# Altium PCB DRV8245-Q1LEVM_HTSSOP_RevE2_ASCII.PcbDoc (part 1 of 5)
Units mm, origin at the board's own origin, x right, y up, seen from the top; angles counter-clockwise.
Board outline 81.9 x 103.6 mm, 4 copper layers (Top Layer, Signal Layer 1, Signal Layer 2, Bottom Layer), stack 1.554 mm thick; 187 components, 116 nets, 590 pads, 1182 vias.
Unrouted connection lines stored in the file: 116.
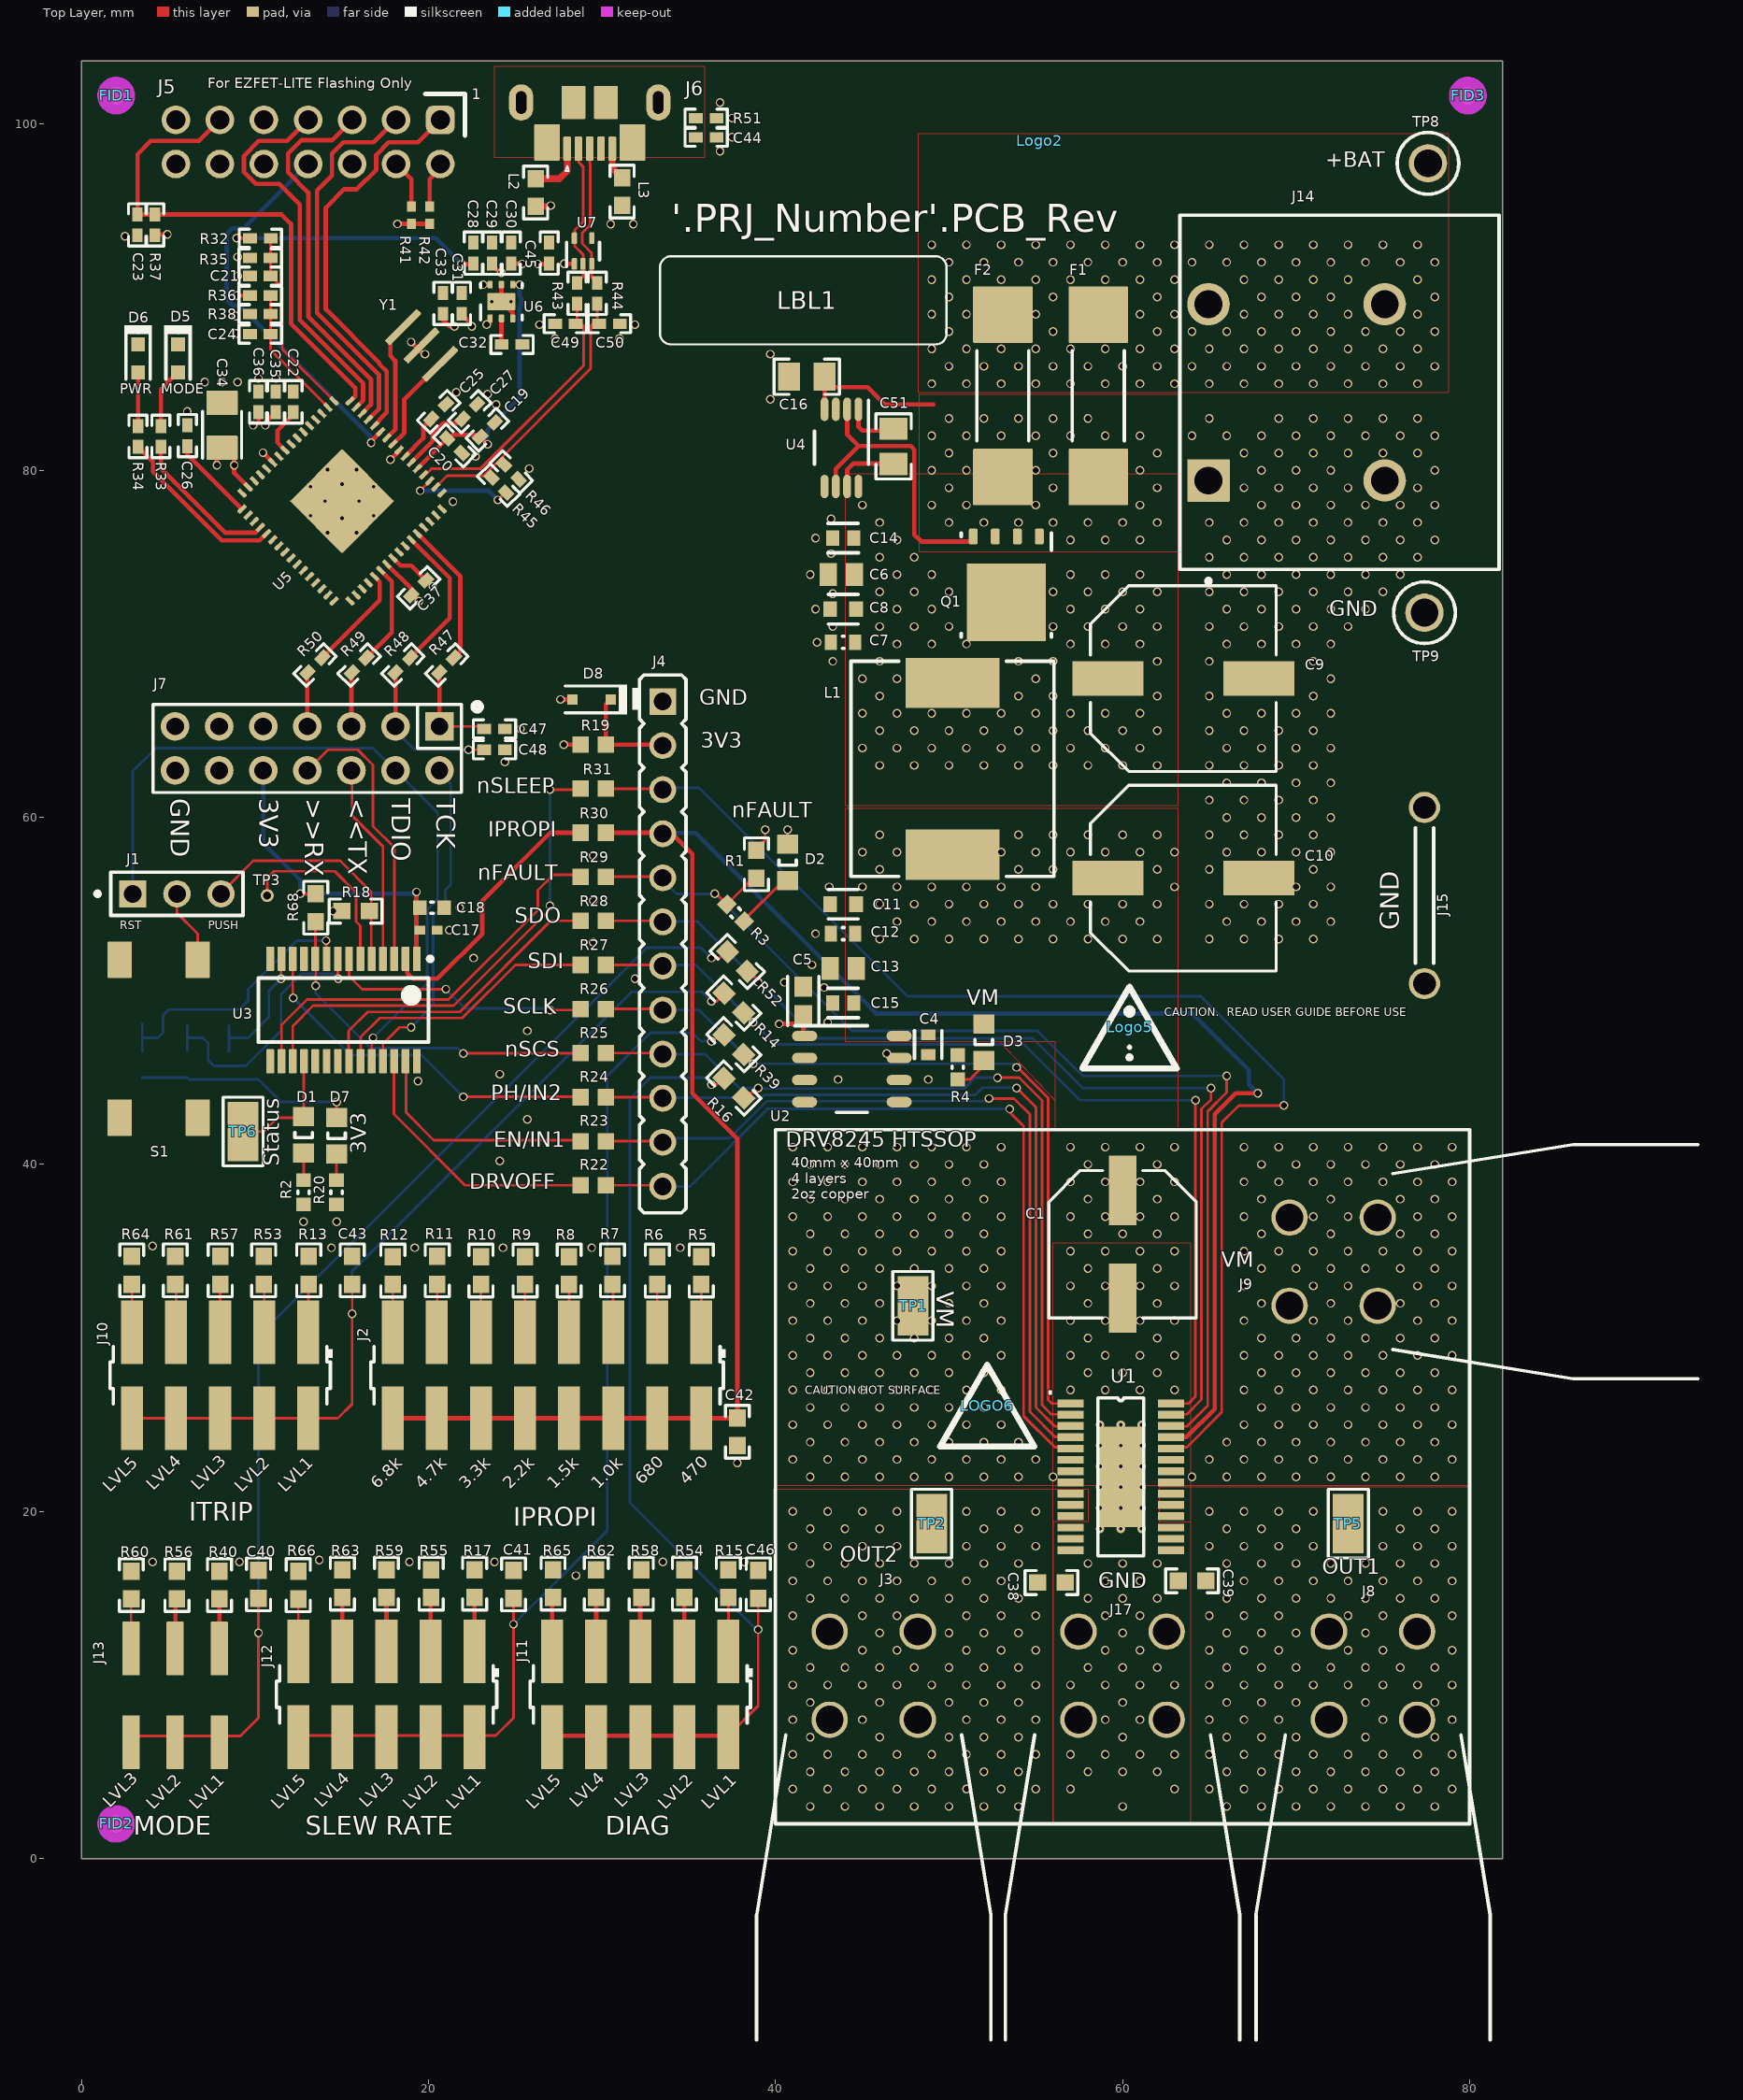
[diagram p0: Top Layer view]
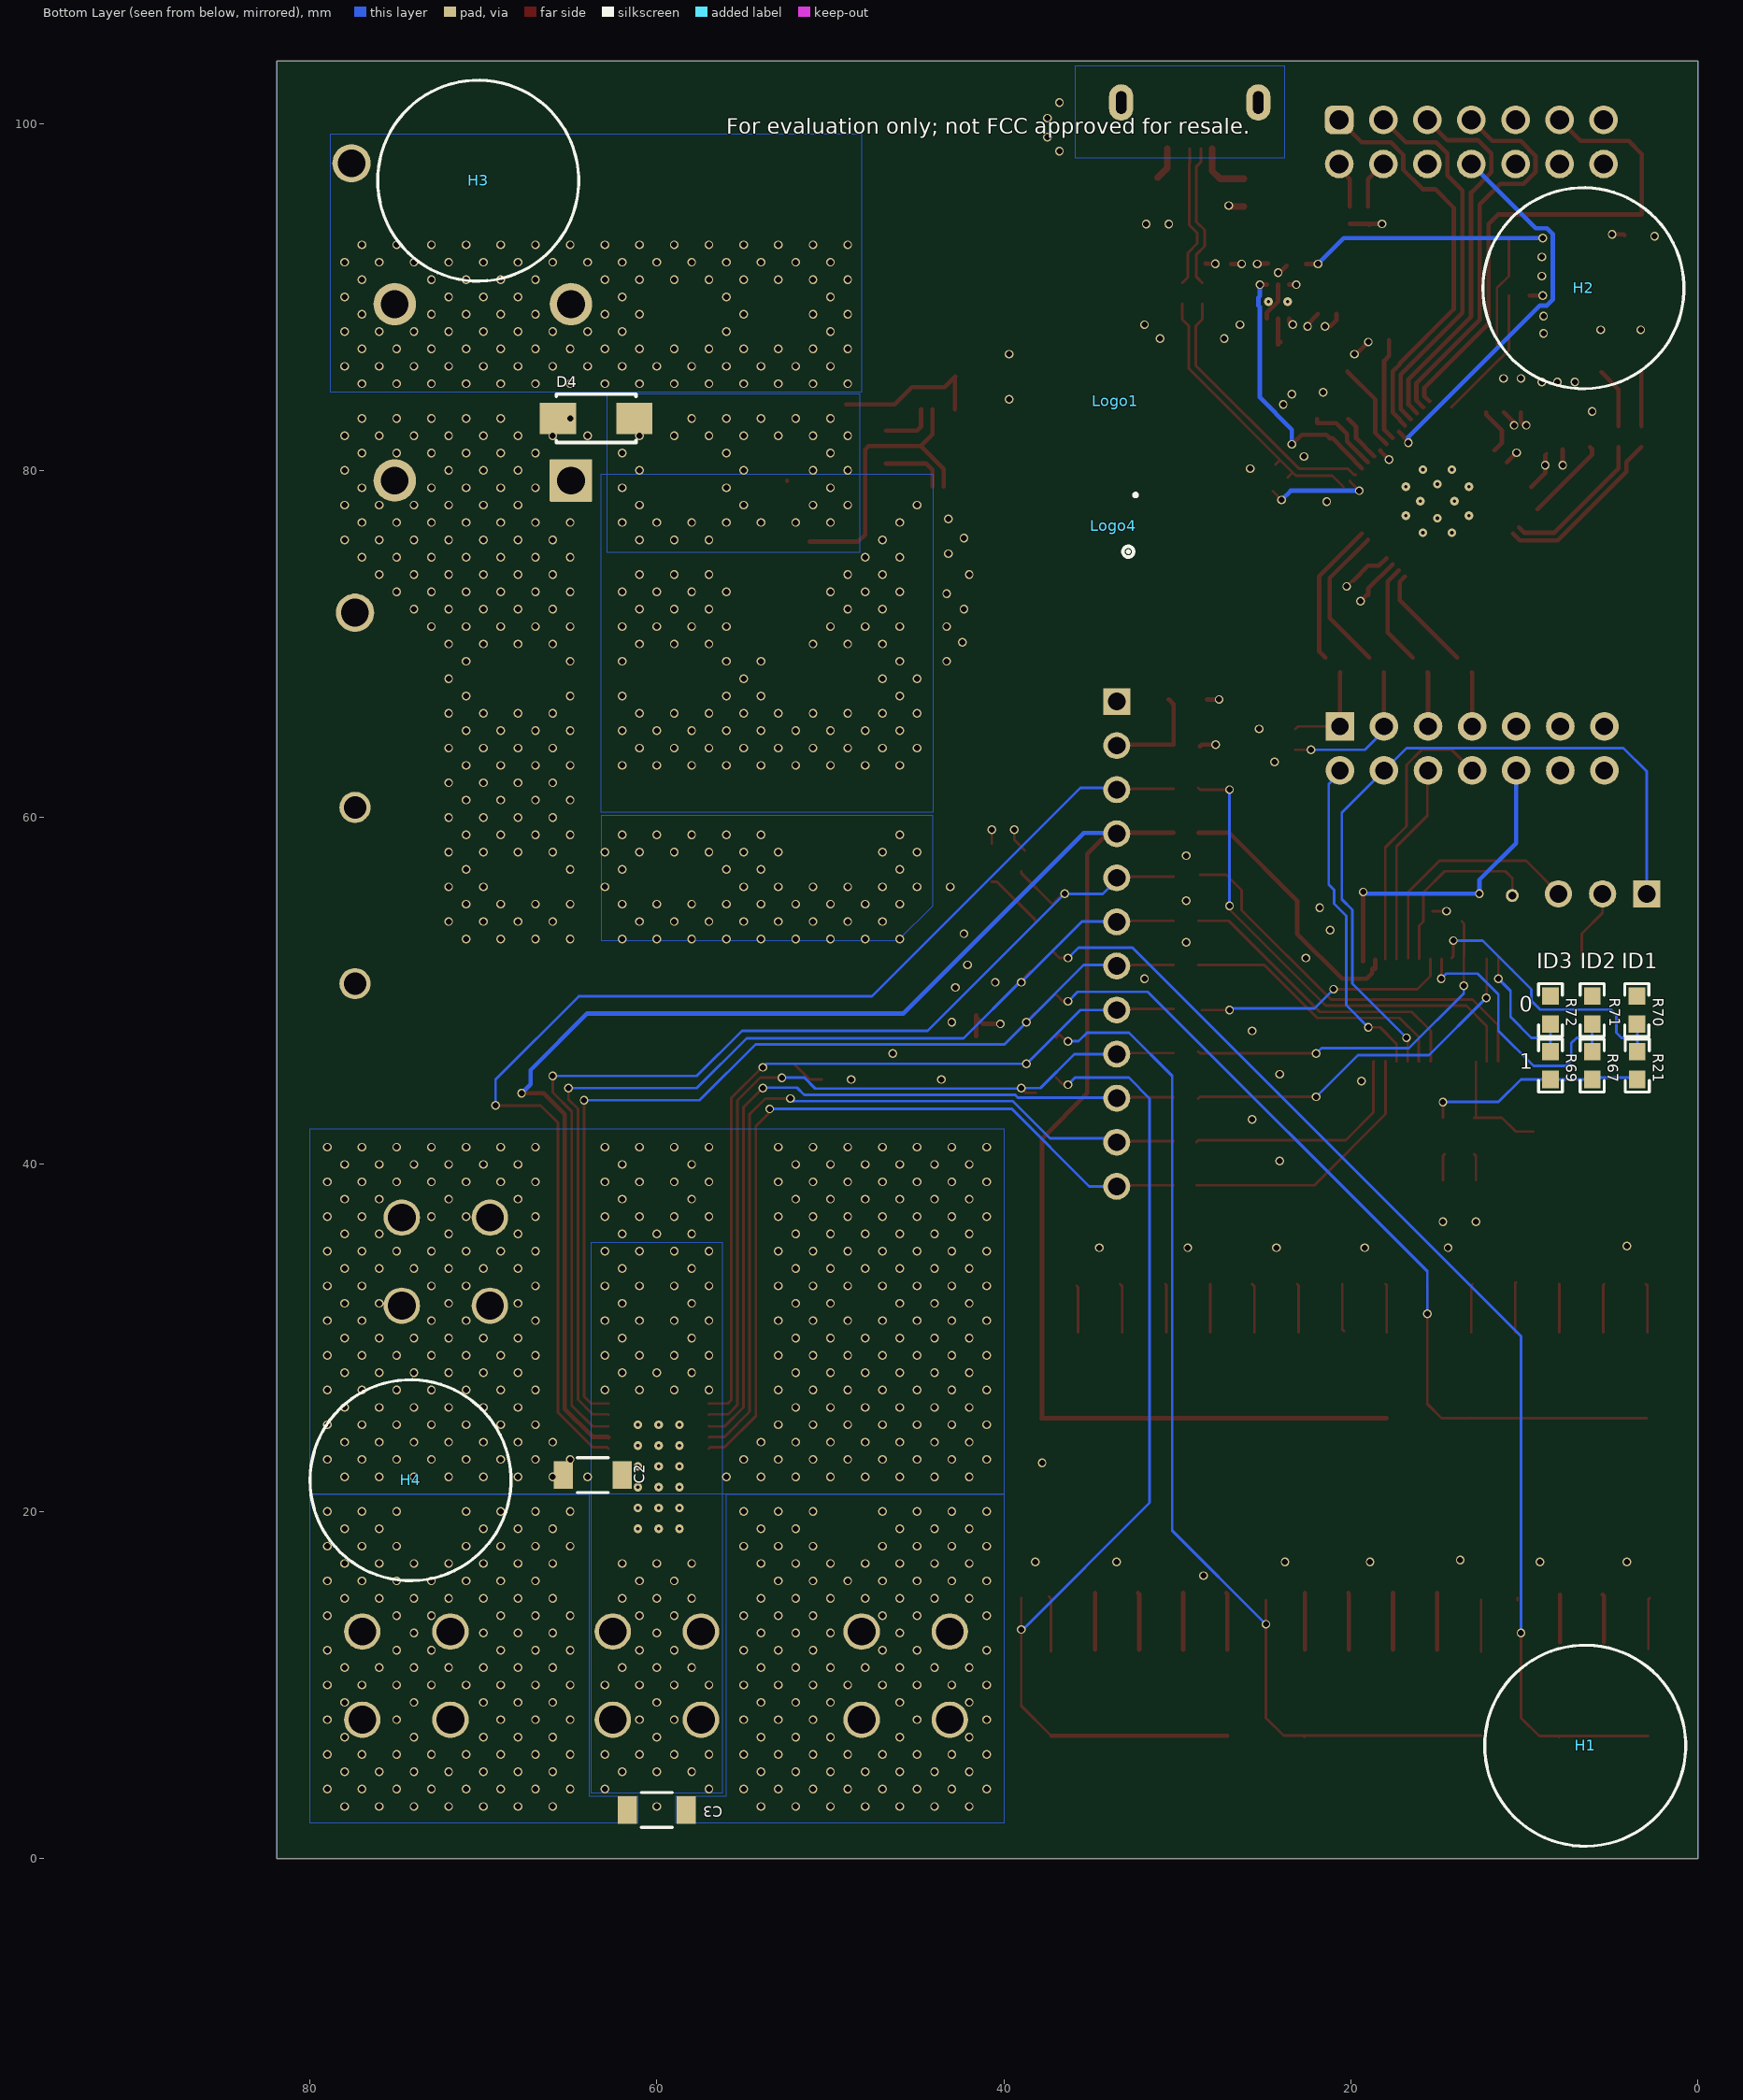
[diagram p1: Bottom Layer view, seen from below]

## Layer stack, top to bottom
Top Solder: solder mask 0.0102, Solder Resist, Dk 3.5
Top Layer: signal copper 0.0711
Dielectric 1: prepreg 0.2896, FR4 370, Dk 4.2
Signal Layer 1: signal copper 0.0356
Dielectric 2: core 0.762, FR4 370, Dk 4.2
Signal Layer 2: signal copper 0.0356
Dielectric 3: prepreg 0.2896, FR4 370, Dk 4.2
Bottom Layer: signal copper 0.0711
Bottom Solder: solder mask 0.0102, Solder Resist, Dk 3.5

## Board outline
0,0 81.9,0 81.9,103.6 0,103.6

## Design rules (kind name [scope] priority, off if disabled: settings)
AcuteAngle [All] p0: scope1count=1 scope1_0_kind=Board scope1_0_value=Board scope2count=1 scope2_0_kind=Board scope2_0_value=Board commentlength=0 minimum=4.50000000000000E+0001
AcuteAngle [All] p1: minimum=4.50000000000000E+0001 checktracksonly=FALSE
AssemblyTestPointUsage [All] p0: scope1count=1 scope1_0_kind=Board scope1_0_value=Board scope2count=1 scope2_0_kind=Board scope2_0_value=Board commentlength=0
AssemblyTestPointUsage [All] p1: valid=2
AssemblyTestpoint [All] p0: scope1count=1 scope1_0_kind=Board scope1_0_value=Board scope2count=1 scope2_0_kind=Board scope2_0_value=Board commentlength=0
BoardOutlineClearance [All] p0 off: scope1count=1 scope1_0_kind=Board scope1_0_value=Board scope2count=1 scope2_0_kind=Board scope2_0_value=Board commentlength=172 gap=1.905 // Protel DXP Scope 1 Expression Was: OnCopper and Not InComponentClass('Logo') and not InComponentClass('FiducialMark') and not InRegion(1000,500,4000,800) and not InPoly
BoardOutlineClearance BoardOutlineClearance_Poly [All] p0 off: scope1count=1 scope1_0_kind=Board scope1_0_value=Board scope2count=1 scope2_0_kind=Board scope2_0_value=Board commentlength=58 gap=0.635 // Protel DXP Scope 1 Expression Was: OnCopper and IsPoly
BoardOutlineClearance BoardOutlineClearance_MountingHoles [All] p0 off: scope1count=1 scope1_0_kind=Board scope1_0_value=Board scope2count=1 scope2_0_kind=Board scope2_0_value=Board commentlength=86 gap=1 // Protel DXP Scope 1 Expression Was: OnCopper and InComponentClass('Mounting Holes')
BoardOutlineClearance BoardOutlineClearance_MountingHoles [OnCopper and InComponentClass('Mounting Holes')] p1: gap=1 ignorepadtopadclearanceinfootprint=FALSE
BoardOutlineClearance BoardOutlineClearance_Poly [OnCopper and IsPoly] p2: gap=0.635 ignorepadtopadclearanceinfootprint=FALSE
BoardOutlineClearance [OnCopper and Not InComponentClass('Logo') and not InComponentClass('FiducialMark') and not InRegion(1000,500,4000,800) and not InPoly] p3: gap=1.905 ignorepadtopadclearanceinfootprint=FALSE
Clearance Clearance_92 [All] p0 off: scope1count=1 scope1_0_kind=Board scope1_0_value=Board scope2count=1 scope2_0_kind=Board scope2_0_value=Board commentlength=74 gap=0.254 // Protel DXP Scope 1 Expression Was: InNamedPolygon('TOP_LAYER_VM_P125')
Clearance Clearance_91 [All] p0 off: scope1count=1 scope1_0_kind=Board scope1_0_value=Board scope2count=1 scope2_0_kind=Board scope2_0_value=Board commentlength=78 gap=0.254 // Protel DXP Scope 1 Expression Was: InNamedPolygon('TOP_LAYER_NONET_P-001')
Clearance Clearance_90 [All] p0 off: scope1count=1 scope1_0_kind=Board scope1_0_value=Board scope2count=1 scope2_0_kind=Board scope2_0_value=Board commentlength=79 gap=0.254 // Protel DXP Scope 1 Expression Was: InNamedPolygon('BOTTOM_LAYER_OUT2_P211')
Clearance Clearance_89 [All] p0 off: scope1count=1 scope1_0_kind=Board scope1_0_value=Board scope2count=1 scope2_0_kind=Board scope2_0_value=Board commentlength=79 gap=0.254 // Protel DXP Scope 1 Expression Was: InNamedPolygon('BOTTOM_LAYER_OUT1_P205')
Clearance Clearance_88 [All] p0 off: scope1count=1 scope1_0_kind=Board scope1_0_value=Board scope2count=1 scope2_0_kind=Board scope2_0_value=Board commentlength=79 gap=0.254 // Protel DXP Scope 1 Expression Was: InNamedPolygon('BOTTOM_LAYER_OUT1_P205')
Clearance Clearance_87 [All] p0 off: scope1count=1 scope1_0_kind=Board scope1_0_value=Board scope2count=1 scope2_0_kind=Board scope2_0_value=Board commentlength=78 gap=0.254 // Protel DXP Scope 1 Expression Was: InNamedPolygon('BOTTOM_LAYER_GND_P204')
Clearance Clearance_86 [All] p0 off: scope1count=1 scope1_0_kind=Board scope1_0_value=Board scope2count=1 scope2_0_kind=Board scope2_0_value=Board commentlength=75 gap=0.254 // Protel DXP Scope 1 Expression Was: InNamedPolygon('TOP_LAYER_GND_P237')
Clearance Clearance_85 [All] p0 off: scope1count=1 scope1_0_kind=Board scope1_0_value=Board scope2count=1 scope2_0_kind=Board scope2_0_value=Board commentlength=74 gap=0.254 // Protel DXP Scope 1 Expression Was: InNamedPolygon('TOP_LAYER_VM_P229')
Clearance Clearance_84 [All] p0 off: scope1count=1 scope1_0_kind=Board scope1_0_value=Board scope2count=1 scope2_0_kind=Board scope2_0_value=Board commentlength=75 gap=0.254 // Protel DXP Scope 1 Expression Was: InNamedPolygon('TOP_LAYER_GND_P086')
Clearance Clearance_83 [All] p0 off: scope1count=1 scope1_0_kind=Board scope1_0_value=Board scope2count=1 scope2_0_kind=Board scope2_0_value=Board commentlength=76 gap=0.1 // Protel DXP Scope 1 Expression Was: InNamedPolygon('TOP_LAYER_OUT1_P221')
Clearance Clearance_82 [All] p0 off: scope1count=1 scope1_0_kind=Board scope1_0_value=Board scope2count=1 scope2_0_kind=Board scope2_0_value=Board commentlength=76 gap=0.254 // Protel DXP Scope 1 Expression Was: InNamedPolygon('TOP_LAYER_OUT2_P173')
Clearance Clearance_81 [All] p0 off: scope1count=1 scope1_0_kind=Board scope1_0_value=Board scope2count=1 scope2_0_kind=Board scope2_0_value=Board commentlength=76 gap=0.254 // Protel DXP Scope 1 Expression Was: InNamedPolygon('TOP_LAYER_OUT2_P173')
Clearance Clearance_80 [All] p0 off: scope1count=1 scope1_0_kind=Board scope1_0_value=Board scope2count=1 scope2_0_kind=Board scope2_0_value=Board commentlength=76 gap=0.254 // Protel DXP Scope 1 Expression Was: InNamedPolygon('TOP_LAYER_OUT2_P173')
Clearance Clearance_79 [All] p0 off: scope1count=1 scope1_0_kind=Board scope1_0_value=Board scope2count=1 scope2_0_kind=Board scope2_0_value=Board commentlength=76 gap=0.254 // Protel DXP Scope 1 Expression Was: InNamedPolygon('TOP_LAYER_OUT1_P221')
Clearance Clearance_78 [All] p0 off: scope1count=1 scope1_0_kind=Board scope1_0_value=Board scope2count=1 scope2_0_kind=Board scope2_0_value=Board commentlength=75 gap=0.254 // Protel DXP Scope 1 Expression Was: InNamedPolygon('TOP_LAYER_GND_P086')
Clearance Clearance_77 [All] p0 off: scope1count=1 scope1_0_kind=Board scope1_0_value=Board scope2count=1 scope2_0_kind=Board scope2_0_value=Board commentlength=76 gap=0.254 // Protel DXP Scope 1 Expression Was: InNamedPolygon('TOP_LAYER_OUT1_P129')
Clearance Clearance_76 [All] p0 off: scope1count=1 scope1_0_kind=Board scope1_0_value=Board scope2count=1 scope2_0_kind=Board scope2_0_value=Board commentlength=76 gap=0.254 // Protel DXP Scope 1 Expression Was: InNamedPolygon('TOP_LAYER_OUT2_P173')
Clearance Clearance_75 [All] p0 off: scope1count=1 scope1_0_kind=Board scope1_0_value=Board scope2count=1 scope2_0_kind=Board scope2_0_value=Board commentlength=74 gap=0.254 // Protel DXP Scope 1 Expression Was: InNamedPolygon('TOP_LAYER_VM_P085')
Clearance Clearance_74 [All] p0 off: scope1count=1 scope1_0_kind=Board scope1_0_value=Board scope2count=1 scope2_0_kind=Board scope2_0_value=Board commentlength=75 gap=0.254 // Protel DXP Scope 1 Expression Was: InNamedPolygon('TOP_LAYER_GND_P121')
Clearance Clearance_73 [All] p0 off: scope1count=1 scope1_0_kind=Board scope1_0_value=Board scope2count=1 scope2_0_kind=Board scope2_0_value=Board commentlength=118 gap=0.05 // Protel DXP Scope 1 Expression Was: InNamedPolygon('TOP_LAYER_OUT1_P129') Or  InNamedPolygon('TOP_LAYER_OUT2_P173')
Clearance Clearance_72 [All] p0 off: scope1count=1 scope1_0_kind=Board scope1_0_value=Board scope2count=1 scope2_0_kind=Board scope2_0_value=Board commentlength=118 gap=0.1 // Protel DXP Scope 1 Expression Was: InNamedPolygon('TOP_LAYER_OUT2_P173') Or  InNamedPolygon('TOP_LAYER_OUT1_P129')
Clearance Clearance_71 [All] p0 off: scope1count=1 scope1_0_kind=Board scope1_0_value=Board scope2count=1 scope2_0_kind=Board scope2_0_value=Board commentlength=76 gap=0.254 // Protel DXP Scope 1 Expression Was: InNamedPolygon('TOP_LAYER_OUT2_P173')
Clearance Clearance_70 [All] p0 off: scope1count=1 scope1_0_kind=Board scope1_0_value=Board scope2count=1 scope2_0_kind=Board scope2_0_value=Board commentlength=76 gap=0.254 // Protel DXP Scope 1 Expression Was: InNamedPolygon('TOP_LAYER_OUT1_P129')
Clearance Clearance_69 [All] p0 off: scope1count=1 scope1_0_kind=Board scope1_0_value=Board scope2count=1 scope2_0_kind=Board scope2_0_value=Board commentlength=76 gap=0.1 // Protel DXP Scope 1 Expression Was: InNamedPolygon('TOP_LAYER_OUT2_P173')
Clearance Clearance_68 [All] p0 off: scope1count=1 scope1_0_kind=Board scope1_0_value=Board scope2count=1 scope2_0_kind=Board scope2_0_value=Board commentlength=76 gap=0.1 // Protel DXP Scope 1 Expression Was: InNamedPolygon('TOP_LAYER_OUT1_P129')
Clearance Clearance_67 [All] p0 off: scope1count=1 scope1_0_kind=Board scope1_0_value=Board scope2count=1 scope2_0_kind=Board scope2_0_value=Board commentlength=74 gap=0.1 // Protel DXP Scope 1 Expression Was: InNamedPolygon('TOP_LAYER_VM_P085')
Clearance Clearance_66 [All] p0 off: scope1count=1 scope1_0_kind=Board scope1_0_value=Board scope2count=1 scope2_0_kind=Board scope2_0_value=Board commentlength=79 gap=0.254 // Protel DXP Scope 1 Expression Was: InNamedPolygon('BOTTOM_LAYER_P_IN_P174')
Clearance Clearance_65 [All] p0 off: scope1count=1 scope1_0_kind=Board scope1_0_value=Board scope2count=1 scope2_0_kind=Board scope2_0_value=Board commentlength=82 gap=0.254 // Protel DXP Scope 1 Expression Was: InNamedPolygon('BOTTOM_LAYER_NETF1_2_P203')
Clearance Clearance_64 [All] p0 off: scope1count=1 scope1_0_kind=Board scope1_0_value=Board scope2count=1 scope2_0_kind=Board scope2_0_value=Board commentlength=79 gap=0.254 // Protel DXP Scope 1 Expression Was: InNamedPolygon('BOTTOM_LAYER_VBAT_P165')
Clearance Clearance_63 [All] p0 off: scope1count=1 scope1_0_kind=Board scope1_0_value=Board scope2count=1 scope2_0_kind=Board scope2_0_value=Board commentlength=74 gap=0.254 // Protel DXP Scope 1 Expression Was: InNamedPolygon('TOP_LAYER_VM_P167')
Clearance Clearance_62 [All] p0 off: scope1count=1 scope1_0_kind=Board scope1_0_value=Board scope2count=1 scope2_0_kind=Board scope2_0_value=Board commentlength=74 gap=0.254 // Protel DXP Scope 1 Expression Was: InNamedPolygon('TOP_LAYER_VM_P167')
Clearance Clearance_61 [All] p0 off: scope1count=1 scope1_0_kind=Board scope1_0_value=Board scope2count=1 scope2_0_kind=Board scope2_0_value=Board commentlength=74 gap=0.254 // Protel DXP Scope 1 Expression Was: InNamedPolygon('TOP_LAYER_VM_P171')
Clearance Clearance_60 [All] p0 off: scope1count=1 scope1_0_kind=Board scope1_0_value=Board scope2count=1 scope2_0_kind=Board scope2_0_value=Board commentlength=84 gap=0.254 // Protel DXP Scope 1 Expression Was: InNamedPolygon('SIGNAL_LAYER_2_NETF1_2_P196')
Clearance Clearance_59 [All] p0 off: scope1count=1 scope1_0_kind=Board scope1_0_value=Board scope2count=1 scope2_0_kind=Board scope2_0_value=Board commentlength=81 gap=0.254 // Protel DXP Scope 1 Expression Was: InNamedPolygon('SIGNAL_LAYER_2_VBAT_P197')
Clearance Clearance_58 [All] p0 off: scope1count=1 scope1_0_kind=Board scope1_0_value=Board scope2count=1 scope2_0_kind=Board scope2_0_value=Board commentlength=81 gap=0.254 // Protel DXP Scope 1 Expression Was: InNamedPolygon('SIGNAL_LAYER_2_P_IN_P198')
Clearance Clearance_57 [All] p0 off: scope1count=1 scope1_0_kind=Board scope1_0_value=Board scope2count=1 scope2_0_kind=Board scope2_0_value=Board commentlength=80 gap=0.254 // Protel DXP Scope 1 Expression Was: InNamedPolygon('SIGNAL_LAYER_2_3V3_P194')
Clearance Clearance_56 [All] p0 off: scope1count=1 scope1_0_kind=Board scope1_0_value=Board scope2count=1 scope2_0_kind=Board scope2_0_value=Board commentlength=79 gap=0.254 // Protel DXP Scope 1 Expression Was: InNamedPolygon('TOP_LAYER_NETF1_2_P207')
Clearance Clearance_55 [All] p0 off: scope1count=1 scope1_0_kind=Board scope1_0_value=Board scope2count=1 scope2_0_kind=Board scope2_0_value=Board commentlength=76 gap=0.254 // Protel DXP Scope 1 Expression Was: InNamedPolygon('TOP_LAYER_VBAT_P223')
Clearance Clearance_54 [All] p0 off: scope1count=1 scope1_0_kind=Board scope1_0_value=Board scope2count=1 scope2_0_kind=Board scope2_0_value=Board commentlength=76 gap=0.254 // Protel DXP Scope 1 Expression Was: InNamedPolygon('TOP_LAYER_P_IN_P227')
Clearance Clearance_53 [All] p0 off: scope1count=1 scope1_0_kind=Board scope1_0_value=Board scope2count=1 scope2_0_kind=Board scope2_0_value=Board commentlength=75 gap=0.254 // Protel DXP Scope 1 Expression Was: InNamedPolygon('TOP_LAYER_GND_P086')
Clearance Clearance_52 [All] p0 off: scope1count=1 scope1_0_kind=Board scope1_0_value=Board scope2count=1 scope2_0_kind=Board scope2_0_value=Board commentlength=259 gap=0.254 // Protel DXP Scope 1 Expression Was: InNamedPolygon('SIGNAL_LAYER_2_VM_P177') Or  InNamedPolygon('SIGNAL_LAYER_2_VM_P179') Or  InNamedPolygon('SIGNAL_LAYER_2_VM_P160') Or  InNamedPolygon('SIGNAL_LAYER_2_VM_P175') Or  InNamedPolygon('SIGNAL_LAYER_2_VM_P181')
Clearance Clearance_51 [All] p0 off: scope1count=1 scope1_0_kind=Board scope1_0_value=Board scope2count=1 scope2_0_kind=Board scope2_0_value=Board commentlength=87 gap=0.254 // Protel DXP Scope 1 Expression Was: InNamedPolygon('SIGNAL_LAYER_2_EZFET_VBUS_P136')
Clearance Clearance_50 [All] p0 off: scope1count=1 scope1_0_kind=Board scope1_0_value=Board scope2count=1 scope2_0_kind=Board scope2_0_value=Board commentlength=86 gap=0.254 // Protel DXP Scope 1 Expression Was: InNamedPolygon('SIGNAL_LAYER_2_EZFET_VCC_P132')
Clearance Clearance_49 [All] p0 off: scope1count=1 scope1_0_kind=Board scope1_0_value=Board scope2count=1 scope2_0_kind=Board scope2_0_value=Board commentlength=84 gap=0.254 // Protel DXP Scope 1 Expression Was: InNamedPolygon('SIGNAL_LAYER_2_3V3_MCU_P192')
Clearance Clearance_48 [All] p0 off: scope1count=1 scope1_0_kind=Board scope1_0_value=Board scope2count=1 scope2_0_kind=Board scope2_0_value=Board commentlength=80 gap=0.254 // Protel DXP Scope 1 Expression Was: InNamedPolygon('SIGNAL_LAYER_1_GND_P190')
Clearance Clearance_47 [All] p0 off: scope1count=1 scope1_0_kind=Board scope1_0_value=Board scope2count=1 scope2_0_kind=Board scope2_0_value=Board commentlength=80 gap=0.254 // Protel DXP Scope 1 Expression Was: InNamedPolygon('SIGNAL_LAYER_1_GND_P184')
Clearance Clearance_46 [All] p0 off: scope1count=1 scope1_0_kind=Board scope1_0_value=Board scope2count=1 scope2_0_kind=Board scope2_0_value=Board commentlength=78 gap=0.254 // Protel DXP Scope 1 Expression Was: InNamedPolygon('BOTTOM_LAYER_GND_P241')
Clearance Clearance_45 [All] p0 off: scope1count=1 scope1_0_kind=Board scope1_0_value=Board scope2count=1 scope2_0_kind=Board scope2_0_value=Board commentlength=78 gap=0.254 // Protel DXP Scope 1 Expression Was: InNamedPolygon('BOTTOM_LAYER_GND_P241')
Clearance Clearance_44 [All] p0 off: scope1count=1 scope1_0_kind=Board scope1_0_value=Board scope2count=1 scope2_0_kind=Board scope2_0_value=Board commentlength=79 gap=0.254 // Protel DXP Scope 1 Expression Was: InNamedPolygon('BOTTOM_LAYER_OUT2_P163')
Clearance Clearance_43 [All] p0 off: scope1count=1 scope1_0_kind=Board scope1_0_value=Board scope2count=1 scope2_0_kind=Board scope2_0_value=Board commentlength=77 gap=0.254 // Protel DXP Scope 1 Expression Was: InNamedPolygon('BOTTOM_LAYER_VM_P166')
Clearance Clearance_42 [All] p0 off: scope1count=1 scope1_0_kind=Board scope1_0_value=Board scope2count=1 scope2_0_kind=Board scope2_0_value=Board commentlength=77 gap=0.254 // Protel DXP Scope 1 Expression Was: InNamedPolygon('BOTTOM_LAYER_VM_P235')
Clearance Clearance_41 [All] p0 off: scope1count=1 scope1_0_kind=Board scope1_0_value=Board scope2count=1 scope2_0_kind=Board scope2_0_value=Board commentlength=79 gap=0.254 // Protel DXP Scope 1 Expression Was: InNamedPolygon('BOTTOM_LAYER_OUT1_P164')
Clearance Clearance_40 [All] p0 off: scope1count=1 scope1_0_kind=Board scope1_0_value=Board scope2count=1 scope2_0_kind=Board scope2_0_value=Board commentlength=78 gap=0.254 // Protel DXP Scope 1 Expression Was: InNamedPolygon('BOTTOM_LAYER_GND_P162')
Clearance Clearance_39 [All] p0 off: scope1count=1 scope1_0_kind=Board scope1_0_value=Board scope2count=1 scope2_0_kind=Board scope2_0_value=Board commentlength=79 gap=0.254 // Protel DXP Scope 1 Expression Was: InNamedPolygon('SIGNAL_LAYER_2_VM_P160')
Clearance Clearance_38 [All] p0 off: scope1count=1 scope1_0_kind=Board scope1_0_value=Board scope2count=1 scope2_0_kind=Board scope2_0_value=Board commentlength=82 gap=0.254 // Protel DXP Scope 1 Expression Was: InNamedPolygon('SIGNAL_LAYER_2_NONET_P138')
Clearance Clearance_37 [All] p0 off: scope1count=1 scope1_0_kind=Board scope1_0_value=Board scope2count=1 scope2_0_kind=Board scope2_0_value=Board commentlength=79 gap=0.254 // Protel DXP Scope 1 Expression Was: InNamedPolygon('SIGNAL_LAYER_1_VM_P146')
Clearance Clearance_36 [All] p0 off: scope1count=1 scope1_0_kind=Board scope1_0_value=Board scope2count=1 scope2_0_kind=Board scope2_0_value=Board commentlength=80 gap=0.254 // Protel DXP Scope 1 Expression Was: InNamedPolygon('SIGNAL_LAYER_2_GND_P156')
Clearance Clearance_35 [All] p0 off: scope1count=1 scope1_0_kind=Board scope1_0_value=Board scope2count=1 scope2_0_kind=Board scope2_0_value=Board commentlength=124 gap=0.254 // Protel DXP Scope 1 Expression Was: InNamedPolygon('SIGNAL_LAYER_1_VM_P148') Or  InNamedPolygon('SIGNAL_LAYER_1_VM_P148')
Clearance Clearance_34 [All] p0 off: scope1count=1 scope1_0_kind=Board scope1_0_value=Board scope2count=1 scope2_0_kind=Board scope2_0_value=Board commentlength=80 gap=0.254 // Protel DXP Scope 1 Expression Was: InNamedPolygon('SIGNAL_LAYER_1_GND_P154')
Clearance Clearance_33 [All] p0 off: scope1count=1 scope1_0_kind=Board scope1_0_value=Board scope2count=1 scope2_0_kind=Board scope2_0_value=Board commentlength=82 gap=0.254 // Protel DXP Scope 1 Expression Was: InNamedPolygon('SIGNAL_LAYER_2_NONET_P138')
Clearance Clearance_32 [All] p0 off: scope1count=1 scope1_0_kind=Board scope1_0_value=Board scope2count=1 scope2_0_kind=Board scope2_0_value=Board commentlength=80 gap=0.254 // Protel DXP Scope 1 Expression Was: InNamedPolygon('SIGNAL_LAYER_2_GND_P082')
Clearance Clearance_31 [All] p0 off: scope1count=1 scope1_0_kind=Board scope1_0_value=Board scope2count=1 scope2_0_kind=Board scope2_0_value=Board commentlength=75 gap=0.254 // Protel DXP Scope 1 Expression Was: InNamedPolygon('TOP_LAYER_GND_P076')
Clearance Clearance_30 [All] p0 off: scope1count=1 scope1_0_kind=Board scope1_0_value=Board scope2count=1 scope2_0_kind=Board scope2_0_value=Board commentlength=75 gap=0.254 // Protel DXP Scope 1 Expression Was: InNamedPolygon('TOP_LAYER_GND_P087')
Clearance Clearance_29 [All] p0 off: scope1count=1 scope1_0_kind=Board scope1_0_value=Board scope2count=1 scope2_0_kind=Board scope2_0_value=Board commentlength=114 gap=0.254 // Protel DXP Scope 1 Expression Was: InNamedPolygon('TOP_LAYER_VM_P127') Or  InNamedPolygon('TOP_LAYER_VM_P085')
Clearance Clearance_28 [All] p0 off: scope1count=1 scope1_0_kind=Board scope1_0_value=Board scope2count=1 scope2_0_kind=Board scope2_0_value=Board commentlength=75 gap=0.254 // Protel DXP Scope 1 Expression Was: InNamedPolygon('TOP_LAYER_GND_P117')
Clearance Clearance_27 [All] p0 off: scope1count=1 scope1_0_kind=Board scope1_0_value=Board scope2count=1 scope2_0_kind=Board scope2_0_value=Board commentlength=118 gap=0.254 // Protel DXP Scope 1 Expression Was: InNamedPolygon('TOP_LAYER_OUT1_P129') Or  InNamedPolygon('TOP_LAYER_OUT2_P173')
Clearance Clearance_26 [All] p0 off: scope1count=1 scope1_0_kind=Board scope1_0_value=Board scope2count=1 scope2_0_kind=Board scope2_0_value=Board commentlength=82 gap=0.254 // Protel DXP Scope 1 Expression Was: InNamedPolygon('SIGNAL_LAYER_2_NONET_P113')
Clearance Clearance_25 [All] p0 off: scope1count=1 scope1_0_kind=Board scope1_0_value=Board scope2count=1 scope2_0_kind=Board scope2_0_value=Board commentlength=80 gap=0.254 // Protel DXP Scope 1 Expression Was: InNamedPolygon('BOTTOM_LAYER_NONET_P115')
Clearance Clearance_24 [All] p0 off: scope1count=1 scope1_0_kind=Board scope1_0_value=Board scope2count=1 scope2_0_kind=Board scope2_0_value=Board commentlength=82 gap=0.254 // Protel DXP Scope 1 Expression Was: InNamedPolygon('SIGNAL_LAYER_1_NONET_P111')
Clearance Clearance_23 [All] p0 off: scope1count=1 scope1_0_kind=Board scope1_0_value=Board scope2count=1 scope2_0_kind=Board scope2_0_value=Board commentlength=77 gap=0.254 // Protel DXP Scope 1 Expression Was: InNamedPolygon('TOP_LAYER_NONET_P083')
Clearance Clearance_22 [All] p0 off: scope1count=1 scope1_0_kind=Board scope1_0_value=Board scope2count=1 scope2_0_kind=Board scope2_0_value=Board commentlength=77 gap=0.254 // Protel DXP Scope 1 Expression Was: InNamedPolygon('TOP_LAYER_NONET_P105')
Clearance Clearance_21 [All] p0 off: scope1count=1 scope1_0_kind=Board scope1_0_value=Board scope2count=1 scope2_0_kind=Board scope2_0_value=Board commentlength=76 gap=0.254 // Protel DXP Scope 1 Expression Was: InNamedPolygon('TOP_LAYER_OUT2_P107')
Clearance Clearance_20 [All] p0 off: scope1count=1 scope1_0_kind=Board scope1_0_value=Board scope2count=1 scope2_0_kind=Board scope2_0_value=Board commentlength=77 gap=0.254 // Protel DXP Scope 1 Expression Was: InNamedPolygon('TOP_LAYER_NONET_P101')
Clearance Clearance_19 [All] p0 off: scope1count=1 scope1_0_kind=Board scope1_0_value=Board scope2count=1 scope2_0_kind=Board scope2_0_value=Board commentlength=76 gap=0.254 // Protel DXP Scope 1 Expression Was: InNamedPolygon('TOP_LAYER_OUT1_P103')
Clearance Clearance_18 [All] p0: scope1count=1 scope1_0_kind=Net scope1_0_value=OUT1 scope2count=1 scope2_0_kind=Board scope2_0_value=Board commentlength=0 gap=0.254
Clearance Clearance_17 [All] p0 off: scope1count=1 scope1_0_kind=Board scope1_0_value=Board scope2count=1 scope2_0_kind=Board scope2_0_value=Board commentlength=76 gap=0.254 // Protel DXP Scope 1 Expression Was: InNamedPolygon('TOP_LAYER_OUT1_P000')
Clearance Clearance_16 [All] p0 off: scope1count=1 scope1_0_kind=Board scope1_0_value=Board scope2count=1 scope2_0_kind=Net scope2_0_value=OUT1 commentlength=76 gap=0.1 // Protel DXP Scope 1 Expression Was: InNamedPolygon('TOP_LAYER_OUT1_P000')
Clearance Clearance_15 [All] p0 off: scope1count=1 scope1_0_kind=Board scope1_0_value=Board scope2count=1 scope2_0_kind=Board scope2_0_value=Board commentlength=76 gap=0.1 // Protel DXP Scope 1 Expression Was: InNamedPolygon('TOP_LAYER_OUT1_P000')
Clearance Clearance_14 [All] p0 off: scope1count=1 scope1_0_kind=Board scope1_0_value=Board scope2count=1 scope2_0_kind=Board scope2_0_value=Board commentlength=77 gap=0.1 // Protel DXP Scope 1 Expression Was: InNamedPolygon('TOP_LAYER_NONET_P093')
Clearance Clearance_13 [All] p0 off: scope1count=1 scope1_0_kind=Board scope1_0_value=Board scope2count=1 scope2_0_kind=Board scope2_0_value=Board commentlength=77 gap=0.254 // Protel DXP Scope 1 Expression Was: InNamedPolygon('TOP_LAYER_NONET_P093')
Clearance Clearance_12 [All] p0 off: scope1count=1 scope1_0_kind=Board scope1_0_value=Board scope2count=1 scope2_0_kind=Board scope2_0_value=Board commentlength=76 gap=0.254 // Protel DXP Scope 1 Expression Was: InNamedPolygon('TOP_LAYER_OUT2_P099')
Clearance Clearance_11 [All] p0 off: scope1count=1 scope1_0_kind=Board scope1_0_value=Board scope2count=1 scope2_0_kind=Board scope2_0_value=Board commentlength=76 gap=0.254 // Protel DXP Scope 1 Expression Was: InNamedPolygon('TOP_LAYER_OUT2_P099')
Clearance Clearance_10 [All] p0 off: scope1count=1 scope1_0_kind=Board scope1_0_value=Board scope2count=1 scope2_0_kind=Board scope2_0_value=Board commentlength=76 gap=0.254 // Protel DXP Scope 1 Expression Was: InNamedPolygon('TOP_LAYER_OUT1_P000')
Clearance Clearance_9 [All] p0 off: scope1count=1 scope1_0_kind=Board scope1_0_value=Board scope2count=1 scope2_0_kind=Board scope2_0_value=Board commentlength=76 gap=0.254 // Protel DXP Scope 1 Expression Was: InNamedPolygon('TOP_LAYER_OUT1_P000')
Clearance Clearance_8 [All] p0 off: scope1count=1 scope1_0_kind=Board scope1_0_value=Board scope2count=1 scope2_0_kind=Board scope2_0_value=Board commentlength=933 gap=0.254 // Protel DXP Scope 1 Expression Was: InNamedPolygon('BOTTOM_LAYER_NONET_P079') Or  InNamedPolygon('SIGNAL_LAYER_2_NONET_P078') Or  InNamedPolygon('SIGNAL_LAYER_1_NONET_P077') Or  InNamedPolygon('TOP_LAYER_NONET_P083') Or  InNamedPolygon('BOTTOM_LAYER_NONET_P072') Or  InNamedPolygon('SIGNAL_LAYER_2_NONET_P070') Or  InNamedPolygon('SIGNAL_LAYER_1_NONET_P059') Or  InNamedPolygon('TOP_LAYER_OUT2_P058') Or  InNamedPolygon('BOTTOM_LAYER_NONET_P056') Or  InNamedPolygon('SIGNAL_LAYER_2_NONET_P054') Or  InNamedPolygon('SIGNAL_LAYER_1_NONET_P052') Or  InNamedPolygon('TOP_LAYER_OUT1_P050') Or  InNamedPolygon('BOTTOM_LAYER_VM_P044') Or  InNamedPolygon('SIGNAL_LAYER_2_VM_P042') Or  InNamedPolygon('SIGNAL_LAYER_1_VM_P040') Or  InNamedPolygon('TOP_LAYER_VM_P038') Or  InNamedPolygon('BOTTOM_LAYER_VM_P036') Or  InNamedPolygon('SIGNAL_LAYER_2_VM_P018') Or  InNamedPolygon('SIGNAL_LAYER_1_VM_P016') Or  InNamedPolygon('TOP_LAYER_VM_P002')
Clearance Clearance_7 [All] p0 off: scope1count=1 scope1_0_kind=Board scope1_0_value=Board scope2count=1 scope2_0_kind=Board scope2_0_value=Board commentlength=120 gap=0.254 // Protel DXP Scope 1 Expression Was: InNamedPolygon('TOP_LAYER_NONET_P089') Or  InNamedPolygon('TOP_LAYER_NONET_P090')
Clearance Clearance_6 [All] p0 off: scope1count=1 scope1_0_kind=Board scope1_0_value=Board scope2count=1 scope2_0_kind=Board scope2_0_value=Board commentlength=250 gap=0.254 // Protel DXP Scope 1 Expression Was: InNamedPolygon('BOTTOM_LAYER_EZFET_USB_SHIELD_P002') Or  InNamedPolygon('TOP_LAYER_EZFET_USB_SHIELD_P201') Or  InNamedPolygon('SIGNAL_LAYER_2_EZFET_VBUS_P018') Or  InNamedPolygon('SIGNAL_LAYER_2_EZFET_VCC_P016')
Clearance Clearance_5 [All] p0 off: scope1count=1 scope1_0_kind=Board scope1_0_value=Board scope2count=1 scope2_0_kind=Board scope2_0_value=Board commentlength=77 gap=0.254 // Protel DXP Scope 1 Expression Was: InNamedPolygon('TOP_LAYER_NONET_P072')
Clearance Clearance_4 [All] p0 off: scope1count=1 scope1_0_kind=Board scope1_0_value=Board scope2count=1 scope2_0_kind=Board scope2_0_value=Board commentlength=154 gap=0.254 // Protel DXP Scope 1 Expression Was: InNamedPolygon('TOP_LAYER_VM_P123') Or  InNamedPolygon('TOP_LAYER_VM_P123') Or  InNamedPolygon('TOP_LAYER_VM_P123')
Clearance Clearance_3 [All] p0 off: scope1count=1 scope1_0_kind=Board scope1_0_value=Board scope2count=1 scope2_0_kind=Board scope2_0_value=Board commentlength=198 gap=0.254 // Protel DXP Scope 1 Expression Was: InNamedPolygon('TOP_LAYER_VM_P042') Or  InNamedPolygon('TOP_LAYER_VM_P044') Or  InNamedPolygon('TOP_LAYER_OUT2_P040') Or  InNamedPolygon('TOP_LAYER_OUT1_P038')
Clearance Clearance_2 [All] p0 off: scope1count=1 scope1_0_kind=Board scope1_0_value=Board scope2count=1 scope2_0_kind=Board scope2_0_value=Board commentlength=76 gap=0.254 // Protel DXP Scope 1 Expression Was: InNamedPolygon('TOP_LAYER_OUT2_P040')
Clearance Clearance_1 [All] p0 off: scope1count=1 scope1_0_kind=Board scope1_0_value=Board scope2count=1 scope2_0_kind=Board scope2_0_value=Board commentlength=74 gap=0.152 // Protel DXP Scope 1 Expression Was: InNamedPolygon('TOP_LAYER_VM_P046')
Clearance [All] p0: scope1count=1 scope1_0_kind=Board scope1_0_value=Board scope2count=1 scope2_0_kind=Board scope2_0_value=Board commentlength=0 gap=0.2
Clearance Clearance_FiducialMark [All] p0 off: scope1count=1 scope1_0_kind=Board scope1_0_value=Board scope2count=1 scope2_0_kind=Board scope2_0_value=Board commentlength=81 gap=0 // Protel DXP Scope 2 Expression Was: IsPad and InComponentClass('FiducialMark')
Clearance Clearance_Poly [All] p0 off: scope1count=1 scope1_0_kind=Board scope1_0_value=Board scope2count=1 scope2_0_kind=Board scope2_0_value=Board commentlength=48 gap=0.635 // Protel DXP Scope 1 Expression Was: InPolygon
Clearance Clearance_Keepouts [All] p0 off: scope1count=1 scope1_0_kind=Board scope1_0_value=Board scope2count=1 scope2_0_kind=Board scope2_0_value=Board commentlength=99 gap=0 // Protel DXP Scope 2 Expression Was: ((IsTrack Or IsArc) And Not InPoly) And IsFree and IsKeepOut
Clearance Clearance_92 [InNamedPolygon('TOP_LAYER_VM_P125')] p1: gap=0.254 ignorepadtopadclearanceinfootprint=TRUE except(0: Arc-Hole Track-Hole SMDPad-Hole THPad-Hole Via-Hole Fill-Hole Poly-Hole Region-Hole Text-Hole)
Clearance Clearance_91 [InNamedPolygon('TOP_LAYER_NONET_P-001')] p2: gap=0.254 ignorepadtopadclearanceinfootprint=TRUE except(0: Arc-Hole Track-Hole SMDPad-Hole THPad-Hole Via-Hole Fill-Hole Poly-Hole Region-Hole Text-Hole)
Clearance Clearance_90 [InNamedPolygon('BOTTOM_LAYER_OUT2_P211')] p3: gap=0.254 ignorepadtopadclearanceinfootprint=TRUE except(0: Arc-Hole Track-Hole SMDPad-Hole THPad-Hole Via-Hole Fill-Hole Poly-Hole Region-Hole Text-Hole)
Clearance Clearance_89 [InNamedPolygon('BOTTOM_LAYER_OUT1_P205')] p4: gap=0.254 ignorepadtopadclearanceinfootprint=TRUE except(0: Arc-Hole Track-Hole SMDPad-Hole THPad-Hole Via-Hole Fill-Hole Poly-Hole Region-Hole Text-Hole)
Clearance Clearance_88 [InNamedPolygon('BOTTOM_LAYER_OUT1_P205')] p5: gap=0.254 ignorepadtopadclearanceinfootprint=TRUE except(0: Arc-Hole Track-Hole SMDPad-Hole THPad-Hole Via-Hole Fill-Hole Poly-Hole Region-Hole Text-Hole)
Clearance Clearance_87 [InNamedPolygon('BOTTOM_LAYER_GND_P204')] p6: gap=0.254 ignorepadtopadclearanceinfootprint=TRUE except(0: Arc-Hole Track-Hole SMDPad-Hole THPad-Hole Via-Hole Fill-Hole Poly-Hole Region-Hole Text-Hole)
Clearance Clearance_86 [InNamedPolygon('TOP_LAYER_GND_P237')] p7: gap=0.254 ignorepadtopadclearanceinfootprint=TRUE except(0: Arc-Hole Track-Hole SMDPad-Hole THPad-Hole Via-Hole Fill-Hole Poly-Hole Region-Hole Text-Hole)
Clearance Clearance_85 [InNamedPolygon('TOP_LAYER_VM_P229')] p8: gap=0.254 ignorepadtopadclearanceinfootprint=TRUE except(0: Arc-Hole Track-Hole SMDPad-Hole THPad-Hole Via-Hole Fill-Hole Poly-Hole Region-Hole Text-Hole)
Clearance Clearance_84 [InNamedPolygon('TOP_LAYER_GND_P086')] p9: gap=0.254 ignorepadtopadclearanceinfootprint=TRUE except(0: Arc-Hole Track-Hole SMDPad-Hole THPad-Hole Via-Hole Fill-Hole Poly-Hole Region-Hole Text-Hole)
Clearance Clearance_83 [InNamedPolygon('TOP_LAYER_OUT1_P221')] p10: gap=0.1 ignorepadtopadclearanceinfootprint=TRUE except(0: Arc-Hole Track-Hole SMDPad-Hole THPad-Hole Via-Hole Fill-Hole Poly-Hole Region-Hole Text-Hole)
Clearance Clearance_82 [InNamedPolygon('TOP_LAYER_OUT2_P173')] p11: gap=0.254 ignorepadtopadclearanceinfootprint=TRUE except(0: Arc-Hole Track-Hole SMDPad-Hole THPad-Hole Via-Hole Fill-Hole Poly-Hole Region-Hole Text-Hole)
Clearance Clearance_81 [InNamedPolygon('TOP_LAYER_OUT2_P173')] p12: gap=0.254 ignorepadtopadclearanceinfootprint=TRUE except(0: Arc-Hole Track-Hole SMDPad-Hole THPad-Hole Via-Hole Fill-Hole Poly-Hole Region-Hole Text-Hole)
Clearance Clearance_80 [InNamedPolygon('TOP_LAYER_OUT2_P173')] p13: gap=0.254 ignorepadtopadclearanceinfootprint=TRUE except(0: Arc-Hole Track-Hole SMDPad-Hole THPad-Hole Via-Hole Fill-Hole Poly-Hole Region-Hole Text-Hole)
Clearance Clearance_79 [InNamedPolygon('TOP_LAYER_OUT1_P221')] p14: gap=0.254 ignorepadtopadclearanceinfootprint=TRUE except(0: Arc-Hole Track-Hole SMDPad-Hole THPad-Hole Via-Hole Fill-Hole Poly-Hole Region-Hole Text-Hole)
Clearance Clearance_78 [InNamedPolygon('TOP_LAYER_GND_P086')] p15: gap=0.254 ignorepadtopadclearanceinfootprint=TRUE except(0: Arc-Hole Track-Hole SMDPad-Hole THPad-Hole Via-Hole Fill-Hole Poly-Hole Region-Hole Text-Hole)
Clearance Clearance_77 [InNamedPolygon('TOP_LAYER_OUT1_P129')] p16: gap=0.254 ignorepadtopadclearanceinfootprint=TRUE except(0: Arc-Hole Track-Hole SMDPad-Hole THPad-Hole Via-Hole Fill-Hole Poly-Hole Region-Hole Text-Hole)
Clearance Clearance_76 [InNamedPolygon('TOP_LAYER_OUT2_P173')] p17: gap=0.254 ignorepadtopadclearanceinfootprint=TRUE except(0: Arc-Hole Track-Hole SMDPad-Hole THPad-Hole Via-Hole Fill-Hole Poly-Hole Region-Hole Text-Hole)
Clearance Clearance_75 [InNamedPolygon('TOP_LAYER_VM_P085')] p18: gap=0.254 ignorepadtopadclearanceinfootprint=TRUE except(0: Arc-Hole Track-Hole SMDPad-Hole THPad-Hole Via-Hole Fill-Hole Poly-Hole Region-Hole Text-Hole)
Clearance Clearance_74 [InNamedPolygon('TOP_LAYER_GND_P121')] p19: gap=0.254 ignorepadtopadclearanceinfootprint=TRUE except(0: Arc-Hole Track-Hole SMDPad-Hole THPad-Hole Via-Hole Fill-Hole Poly-Hole Region-Hole Text-Hole)
Clearance Clearance_73 [InNamedPolygon('TOP_LAYER_OUT1_P129') Or  InNamedPolygon('TOP_LAYER_OUT2_P173')] p20: gap=0.05 ignorepadtopadclearanceinfootprint=TRUE except(0: Arc-Hole Track-Hole SMDPad-Hole THPad-Hole Via-Hole Fill-Hole Poly-Hole Region-Hole Text-Hole)
Clearance Clearance_72 [InNamedPolygon('TOP_LAYER_OUT2_P173') Or  InNamedPolygon('TOP_LAYER_OUT1_P129')] p21: gap=0.1 ignorepadtopadclearanceinfootprint=TRUE except(0: Arc-Hole Track-Hole SMDPad-Hole THPad-Hole Via-Hole Fill-Hole Poly-Hole Region-Hole Text-Hole)
Clearance Clearance_71 [InNamedPolygon('TOP_LAYER_OUT2_P173')] p22: gap=0.254 ignorepadtopadclearanceinfootprint=TRUE except(0: Arc-Hole Track-Hole SMDPad-Hole THPad-Hole Via-Hole Fill-Hole Poly-Hole Region-Hole Text-Hole)
Clearance Clearance_70 [InNamedPolygon('TOP_LAYER_OUT1_P129')] p23: gap=0.254 ignorepadtopadclearanceinfootprint=TRUE except(0: Arc-Hole Track-Hole SMDPad-Hole THPad-Hole Via-Hole Fill-Hole Poly-Hole Region-Hole Text-Hole)
Clearance Clearance_69 [InNamedPolygon('TOP_LAYER_OUT2_P173')] p24: gap=0.1 ignorepadtopadclearanceinfootprint=TRUE except(0: Arc-Hole Track-Hole SMDPad-Hole THPad-Hole Via-Hole Fill-Hole Poly-Hole Region-Hole Text-Hole)
Clearance Clearance_68 [InNamedPolygon('TOP_LAYER_OUT1_P129')] p25: gap=0.1 ignorepadtopadclearanceinfootprint=TRUE except(0: Arc-Hole Track-Hole SMDPad-Hole THPad-Hole Via-Hole Fill-Hole Poly-Hole Region-Hole Text-Hole)
Clearance Clearance_67 [InNamedPolygon('TOP_LAYER_VM_P085')] p26: gap=0.1 ignorepadtopadclearanceinfootprint=TRUE except(0: Arc-Hole Track-Hole SMDPad-Hole THPad-Hole Via-Hole Fill-Hole Poly-Hole Region-Hole Text-Hole)
Clearance Clearance_66 [InNamedPolygon('BOTTOM_LAYER_P_IN_P174')] p27: gap=0.254 ignorepadtopadclearanceinfootprint=TRUE except(0: Arc-Hole Track-Hole SMDPad-Hole THPad-Hole Via-Hole Fill-Hole Poly-Hole Region-Hole Text-Hole)
Clearance Clearance_65 [InNamedPolygon('BOTTOM_LAYER_NETF1_2_P203')] p28: gap=0.254 ignorepadtopadclearanceinfootprint=TRUE except(0: Arc-Hole Track-Hole SMDPad-Hole THPad-Hole Via-Hole Fill-Hole Poly-Hole Region-Hole Text-Hole)
Clearance Clearance_64 [InNamedPolygon('BOTTOM_LAYER_VBAT_P165')] p29: gap=0.254 ignorepadtopadclearanceinfootprint=TRUE except(0: Arc-Hole Track-Hole SMDPad-Hole THPad-Hole Via-Hole Fill-Hole Poly-Hole Region-Hole Text-Hole)
Clearance Clearance_63 [InNamedPolygon('TOP_LAYER_VM_P167')] p30: gap=0.254 ignorepadtopadclearanceinfootprint=TRUE except(0: Arc-Hole Track-Hole SMDPad-Hole THPad-Hole Via-Hole Fill-Hole Poly-Hole Region-Hole Text-Hole)
Clearance Clearance_62 [InNamedPolygon('TOP_LAYER_VM_P167')] p31: gap=0.254 ignorepadtopadclearanceinfootprint=TRUE except(0: Arc-Hole Track-Hole SMDPad-Hole THPad-Hole Via-Hole Fill-Hole Poly-Hole Region-Hole Text-Hole)
Clearance Clearance_61 [InNamedPolygon('TOP_LAYER_VM_P171')] p32: gap=0.254 ignorepadtopadclearanceinfootprint=TRUE except(0: Arc-Hole Track-Hole SMDPad-Hole THPad-Hole Via-Hole Fill-Hole Poly-Hole Region-Hole Text-Hole)
Clearance Clearance_60 [InNamedPolygon('SIGNAL_LAYER_2_NETF1_2_P196')] p33: gap=0.254 ignorepadtopadclearanceinfootprint=TRUE except(0: Arc-Hole Track-Hole SMDPad-Hole THPad-Hole Via-Hole Fill-Hole Poly-Hole Region-Hole Text-Hole)
Clearance Clearance_59 [InNamedPolygon('SIGNAL_LAYER_2_VBAT_P197')] p34: gap=0.254 ignorepadtopadclearanceinfootprint=TRUE except(0: Arc-Hole Track-Hole SMDPad-Hole THPad-Hole Via-Hole Fill-Hole Poly-Hole Region-Hole Text-Hole)
Clearance Clearance_58 [InNamedPolygon('SIGNAL_LAYER_2_P_IN_P198')] p35: gap=0.254 ignorepadtopadclearanceinfootprint=TRUE except(0: Arc-Hole Track-Hole SMDPad-Hole THPad-Hole Via-Hole Fill-Hole Poly-Hole Region-Hole Text-Hole)
Clearance Clearance_57 [InNamedPolygon('SIGNAL_LAYER_2_3V3_P194')] p36: gap=0.254 ignorepadtopadclearanceinfootprint=TRUE except(0: Arc-Hole Track-Hole SMDPad-Hole THPad-Hole Via-Hole Fill-Hole Poly-Hole Region-Hole Text-Hole)
Clearance Clearance_56 [InNamedPolygon('TOP_LAYER_NETF1_2_P207')] p37: gap=0.254 ignorepadtopadclearanceinfootprint=TRUE except(0: Arc-Hole Track-Hole SMDPad-Hole THPad-Hole Via-Hole Fill-Hole Poly-Hole Region-Hole Text-Hole)
Clearance Clearance_55 [InNamedPolygon('TOP_LAYER_VBAT_P223')] p38: gap=0.254 ignorepadtopadclearanceinfootprint=TRUE except(0: Arc-Hole Track-Hole SMDPad-Hole THPad-Hole Via-Hole Fill-Hole Poly-Hole Region-Hole Text-Hole)
Clearance Clearance_54 [InNamedPolygon('TOP_LAYER_P_IN_P227')] p39: gap=0.254 ignorepadtopadclearanceinfootprint=TRUE except(0: Arc-Hole Track-Hole SMDPad-Hole THPad-Hole Via-Hole Fill-Hole Poly-Hole Region-Hole Text-Hole)
Clearance Clearance_53 [InNamedPolygon('TOP_LAYER_GND_P086')] p40: gap=0.254 ignorepadtopadclearanceinfootprint=TRUE except(0: Arc-Hole Track-Hole SMDPad-Hole THPad-Hole Via-Hole Fill-Hole Poly-Hole Region-Hole Text-Hole)
Clearance Clearance_52 [InNamedPolygon('SIGNAL_LAYER_2_VM_P177') Or  InNamedPolygon('SIGNAL_LAYER_2_VM_P179') Or  InNamedPolygon('SIGNAL_LAYER_2_VM_P160') Or  InNamedPolygon('SIGNAL_LAYER_2_VM_P175') Or  InNamedPolygon('SIGNAL_LAYER_2_VM_P181')] p41: gap=0.254 ignorepadtopadclearanceinfootprint=TRUE except(0: Arc-Hole Track-Hole SMDPad-Hole THPad-Hole Via-Hole Fill-Hole Poly-Hole Region-Hole Text-Hole)
Clearance Clearance_51 [InNamedPolygon('SIGNAL_LAYER_2_EZFET_VBUS_P136')] p42: gap=0.254 ignorepadtopadclearanceinfootprint=TRUE except(0: Arc-Hole Track-Hole SMDPad-Hole THPad-Hole Via-Hole Fill-Hole Poly-Hole Region-Hole Text-Hole)
Clearance Clearance_50 [InNamedPolygon('SIGNAL_LAYER_2_EZFET_VCC_P132')] p43: gap=0.254 ignorepadtopadclearanceinfootprint=TRUE except(0: Arc-Hole Track-Hole SMDPad-Hole THPad-Hole Via-Hole Fill-Hole Poly-Hole Region-Hole Text-Hole)
Clearance Clearance_49 [InNamedPolygon('SIGNAL_LAYER_2_3V3_MCU_P192')] p44: gap=0.254 ignorepadtopadclearanceinfootprint=TRUE except(0: Arc-Hole Track-Hole SMDPad-Hole THPad-Hole Via-Hole Fill-Hole Poly-Hole Region-Hole Text-Hole)
Clearance Clearance_48 [InNamedPolygon('SIGNAL_LAYER_1_GND_P190')] p45: gap=0.254 ignorepadtopadclearanceinfootprint=TRUE except(0: Arc-Hole Track-Hole SMDPad-Hole THPad-Hole Via-Hole Fill-Hole Poly-Hole Region-Hole Text-Hole)
Clearance Clearance_47 [InNamedPolygon('SIGNAL_LAYER_1_GND_P184')] p46: gap=0.254 ignorepadtopadclearanceinfootprint=TRUE except(0: Arc-Hole Track-Hole SMDPad-Hole THPad-Hole Via-Hole Fill-Hole Poly-Hole Region-Hole Text-Hole)
Clearance Clearance_46 [InNamedPolygon('BOTTOM_LAYER_GND_P241')] p47: gap=0.254 ignorepadtopadclearanceinfootprint=TRUE except(0: Arc-Hole Track-Hole SMDPad-Hole THPad-Hole Via-Hole Fill-Hole Poly-Hole Region-Hole Text-Hole)
Clearance Clearance_45 [InNamedPolygon('BOTTOM_LAYER_GND_P241')] p48: gap=0.254 ignorepadtopadclearanceinfootprint=TRUE except(0: Arc-Hole Track-Hole SMDPad-Hole THPad-Hole Via-Hole Fill-Hole Poly-Hole Region-Hole Text-Hole)
Clearance Clearance_44 [InNamedPolygon('BOTTOM_LAYER_OUT2_P163')] p49: gap=0.254 ignorepadtopadclearanceinfootprint=TRUE except(0: Arc-Hole Track-Hole SMDPad-Hole THPad-Hole Via-Hole Fill-Hole Poly-Hole Region-Hole Text-Hole)
Clearance Clearance_43 [InNamedPolygon('BOTTOM_LAYER_VM_P166')] p50: gap=0.254 ignorepadtopadclearanceinfootprint=TRUE except(0: Arc-Hole Track-Hole SMDPad-Hole THPad-Hole Via-Hole Fill-Hole Poly-Hole Region-Hole Text-Hole)
Clearance Clearance_42 [InNamedPolygon('BOTTOM_LAYER_VM_P235')] p51: gap=0.254 ignorepadtopadclearanceinfootprint=TRUE except(0: Arc-Hole Track-Hole SMDPad-Hole THPad-Hole Via-Hole Fill-Hole Poly-Hole Region-Hole Text-Hole)
Clearance Clearance_41 [InNamedPolygon('BOTTOM_LAYER_OUT1_P164')] p52: gap=0.254 ignorepadtopadclearanceinfootprint=TRUE except(0: Arc-Hole Track-Hole SMDPad-Hole THPad-Hole Via-Hole Fill-Hole Poly-Hole Region-Hole Text-Hole)
Clearance Clearance_40 [InNamedPolygon('BOTTOM_LAYER_GND_P162')] p53: gap=0.254 ignorepadtopadclearanceinfootprint=TRUE except(0: Arc-Hole Track-Hole SMDPad-Hole THPad-Hole Via-Hole Fill-Hole Poly-Hole Region-Hole Text-Hole)
Clearance Clearance_39 [InNamedPolygon('SIGNAL_LAYER_2_VM_P160')] p54: gap=0.254 ignorepadtopadclearanceinfootprint=TRUE except(0: Arc-Hole Track-Hole SMDPad-Hole THPad-Hole Via-Hole Fill-Hole Poly-Hole Region-Hole Text-Hole)
Clearance Clearance_38 [InNamedPolygon('SIGNAL_LAYER_2_NONET_P138')] p55: gap=0.254 ignorepadtopadclearanceinfootprint=TRUE except(0: Arc-Hole Track-Hole SMDPad-Hole THPad-Hole Via-Hole Fill-Hole Poly-Hole Region-Hole Text-Hole)
Clearance Clearance_37 [InNamedPolygon('SIGNAL_LAYER_1_VM_P146')] p56: gap=0.254 ignorepadtopadclearanceinfootprint=TRUE except(0: Arc-Hole Track-Hole SMDPad-Hole THPad-Hole Via-Hole Fill-Hole Poly-Hole Region-Hole Text-Hole)
Clearance Clearance_36 [InNamedPolygon('SIGNAL_LAYER_2_GND_P156')] p57: gap=0.254 ignorepadtopadclearanceinfootprint=TRUE except(0: Arc-Hole Track-Hole SMDPad-Hole THPad-Hole Via-Hole Fill-Hole Poly-Hole Region-Hole Text-Hole)
Clearance Clearance_35 [InNamedPolygon('SIGNAL_LAYER_1_VM_P148') Or  InNamedPolygon('SIGNAL_LAYER_1_VM_P148')] p58: gap=0.254 ignorepadtopadclearanceinfootprint=TRUE except(0: Arc-Hole Track-Hole SMDPad-Hole THPad-Hole Via-Hole Fill-Hole Poly-Hole Region-Hole Text-Hole)
Clearance Clearance_34 [InNamedPolygon('SIGNAL_LAYER_1_GND_P154')] p59: gap=0.254 ignorepadtopadclearanceinfootprint=TRUE except(0: Arc-Hole Track-Hole SMDPad-Hole THPad-Hole Via-Hole Fill-Hole Poly-Hole Region-Hole Text-Hole)
Clearance Clearance_33 [InNamedPolygon('SIGNAL_LAYER_2_NONET_P138')] p60: gap=0.254 ignorepadtopadclearanceinfootprint=TRUE except(0: Arc-Hole Track-Hole SMDPad-Hole THPad-Hole Via-Hole Fill-Hole Poly-Hole Region-Hole Text-Hole)
Clearance Clearance_32 [InNamedPolygon('SIGNAL_LAYER_2_GND_P082')] p61: gap=0.254 ignorepadtopadclearanceinfootprint=TRUE except(0: Arc-Hole Track-Hole SMDPad-Hole THPad-Hole Via-Hole Fill-Hole Poly-Hole Region-Hole Text-Hole)
Clearance Clearance_31 [InNamedPolygon('TOP_LAYER_GND_P076')] p62: gap=0.254 ignorepadtopadclearanceinfootprint=TRUE except(0: Arc-Hole Track-Hole SMDPad-Hole THPad-Hole Via-Hole Fill-Hole Poly-Hole Region-Hole Text-Hole)
Clearance Clearance_30 [InNamedPolygon('TOP_LAYER_GND_P087')] p63: gap=0.254 ignorepadtopadclearanceinfootprint=TRUE except(0: Arc-Hole Track-Hole SMDPad-Hole THPad-Hole Via-Hole Fill-Hole Poly-Hole Region-Hole Text-Hole)
Clearance Clearance_29 [InNamedPolygon('TOP_LAYER_VM_P127') Or  InNamedPolygon('TOP_LAYER_VM_P085')] p64: gap=0.254 ignorepadtopadclearanceinfootprint=TRUE except(0: Arc-Hole Track-Hole SMDPad-Hole THPad-Hole Via-Hole Fill-Hole Poly-Hole Region-Hole Text-Hole)
Clearance Clearance_28 [InNamedPolygon('TOP_LAYER_GND_P117')] p65: gap=0.254 ignorepadtopadclearanceinfootprint=TRUE except(0: Arc-Hole Track-Hole SMDPad-Hole THPad-Hole Via-Hole Fill-Hole Poly-Hole Region-Hole Text-Hole)
Clearance Clearance_27 [InNamedPolygon('TOP_LAYER_OUT1_P129') Or  InNamedPolygon('TOP_LAYER_OUT2_P173')] p66: gap=0.254 ignorepadtopadclearanceinfootprint=TRUE except(0: Arc-Hole Track-Hole SMDPad-Hole THPad-Hole Via-Hole Fill-Hole Poly-Hole Region-Hole Text-Hole)
Clearance Clearance_26 [InNamedPolygon('SIGNAL_LAYER_2_NONET_P113')] p67: gap=0.254 ignorepadtopadclearanceinfootprint=TRUE except(0: Arc-Hole Track-Hole SMDPad-Hole THPad-Hole Via-Hole Fill-Hole Poly-Hole Region-Hole Text-Hole)
Clearance Clearance_25 [InNamedPolygon('BOTTOM_LAYER_NONET_P115')] p68: gap=0.254 ignorepadtopadclearanceinfootprint=TRUE except(0: Arc-Hole Track-Hole SMDPad-Hole THPad-Hole Via-Hole Fill-Hole Poly-Hole Region-Hole Text-Hole)
Clearance Clearance_24 [InNamedPolygon('SIGNAL_LAYER_1_NONET_P111')] p69: gap=0.254 ignorepadtopadclearanceinfootprint=TRUE except(0: Arc-Hole Track-Hole SMDPad-Hole THPad-Hole Via-Hole Fill-Hole Poly-Hole Region-Hole Text-Hole)
Clearance Clearance_23 [InNamedPolygon('TOP_LAYER_NONET_P083')] p70: gap=0.254 ignorepadtopadclearanceinfootprint=TRUE except(0: Arc-Hole Track-Hole SMDPad-Hole THPad-Hole Via-Hole Fill-Hole Poly-Hole Region-Hole Text-Hole)
Clearance Clearance_22 [InNamedPolygon('TOP_LAYER_NONET_P105')] p71: gap=0.254 ignorepadtopadclearanceinfootprint=TRUE except(0: Arc-Hole Track-Hole SMDPad-Hole THPad-Hole Via-Hole Fill-Hole Poly-Hole Region-Hole Text-Hole)
Clearance Clearance_21 [InNamedPolygon('TOP_LAYER_OUT2_P107')] p72: gap=0.254 ignorepadtopadclearanceinfootprint=TRUE except(0: Arc-Hole Track-Hole SMDPad-Hole THPad-Hole Via-Hole Fill-Hole Poly-Hole Region-Hole Text-Hole)
Clearance Clearance_20 [InNamedPolygon('TOP_LAYER_NONET_P101')] p73: gap=0.254 ignorepadtopadclearanceinfootprint=TRUE except(0: Arc-Hole Track-Hole SMDPad-Hole THPad-Hole Via-Hole Fill-Hole Poly-Hole Region-Hole Text-Hole)
Clearance Clearance_19 [InNamedPolygon('TOP_LAYER_OUT1_P103')] p74: gap=0.254 ignorepadtopadclearanceinfootprint=TRUE except(0: Arc-Hole Track-Hole SMDPad-Hole THPad-Hole Via-Hole Fill-Hole Poly-Hole Region-Hole Text-Hole)
Clearance Clearance_18 [InNet('OUT1')] p75: gap=0.254 ignorepadtopadclearanceinfootprint=TRUE except(0: Arc-Hole Track-Hole SMDPad-Hole THPad-Hole Via-Hole Fill-Hole Poly-Hole Region-Hole Text-Hole)
Clearance Clearance_17 [InNamedPolygon('TOP_LAYER_OUT1_P000')] p76: gap=0.254 ignorepadtopadclearanceinfootprint=TRUE except(0: Arc-Hole Track-Hole SMDPad-Hole THPad-Hole Via-Hole Fill-Hole Poly-Hole Region-Hole Text-Hole)
Clearance Clearance_16 [InNamedPolygon('TOP_LAYER_OUT1_P000') vs InNet('OUT1')] p77: gap=0.1 ignorepadtopadclearanceinfootprint=TRUE except(0: Arc-Hole Track-Hole SMDPad-Hole THPad-Hole Via-Hole Fill-Hole Poly-Hole Region-Hole Text-Hole)
Clearance Clearance_15 [InNamedPolygon('TOP_LAYER_OUT1_P000')] p78: gap=0.1 ignorepadtopadclearanceinfootprint=TRUE except(0: Arc-Hole Track-Hole SMDPad-Hole THPad-Hole Via-Hole Fill-Hole Poly-Hole Region-Hole Text-Hole)
Clearance Clearance_14 [InNamedPolygon('TOP_LAYER_NONET_P093')] p79: gap=0.1 ignorepadtopadclearanceinfootprint=TRUE except(0: Arc-Hole Track-Hole SMDPad-Hole THPad-Hole Via-Hole Fill-Hole Poly-Hole Region-Hole Text-Hole)
Clearance Clearance_13 [InNamedPolygon('TOP_LAYER_NONET_P093')] p80: gap=0.254 ignorepadtopadclearanceinfootprint=TRUE except(0: Arc-Hole Track-Hole SMDPad-Hole THPad-Hole Via-Hole Fill-Hole Poly-Hole Region-Hole Text-Hole)
Clearance Clearance_12 [InNamedPolygon('TOP_LAYER_OUT2_P099')] p81: gap=0.254 ignorepadtopadclearanceinfootprint=TRUE except(0: Arc-Hole Track-Hole SMDPad-Hole THPad-Hole Via-Hole Fill-Hole Poly-Hole Region-Hole Text-Hole)
Clearance Clearance_11 [InNamedPolygon('TOP_LAYER_OUT2_P099')] p82: gap=0.254 ignorepadtopadclearanceinfootprint=TRUE except(0: Arc-Hole Track-Hole SMDPad-Hole THPad-Hole Via-Hole Fill-Hole Poly-Hole Region-Hole Text-Hole)
Clearance Clearance_10 [InNamedPolygon('TOP_LAYER_OUT1_P000')] p83: gap=0.254 ignorepadtopadclearanceinfootprint=TRUE except(0: Arc-Hole Track-Hole SMDPad-Hole THPad-Hole Via-Hole Fill-Hole Poly-Hole Region-Hole Text-Hole)
Clearance Clearance_9 [InNamedPolygon('TOP_LAYER_OUT1_P000')] p84: gap=0.254 ignorepadtopadclearanceinfootprint=TRUE except(0: Arc-Hole Track-Hole SMDPad-Hole THPad-Hole Via-Hole Fill-Hole Poly-Hole Region-Hole Text-Hole)
Clearance Clearance_8 [InNamedPolygon('BOTTOM_LAYER_NONET_P079') Or  InNamedPolygon('SIGNAL_LAYER_2_NONET_P078') Or  InNamedPolygon('SIGNAL_LAYER_1_NONET_P077') Or  InNamedPolygon('TOP_LAYER_NONET_P083') Or  InNamedPolygon('BOTTOM_LAYER_NONET_P072') Or  InNamedPolygon('SIGNAL_LAYER_2_NONET_P070') Or  InNamedPolygon('SIGNAL_LAYER_1_NONET_P059') Or  InNamedPolygon('TOP_LAYER_OUT2_P058') Or  InNamedPolygon('BOTTOM_LAYER_NONET_P056') Or  InNamedPolygon('SIGNAL_LAYER_2_NONET_P054') Or  InNamedPolygon('SIGNAL_LAYER_1_NONET_P052') Or  InNamedPolygon('TOP_LAYER_OUT1_P050') Or  InNamedPolygon('BOTTOM_LAYER_VM_P044') Or  InNamedPolygon('SIGNAL_LAYER_2_VM_P042') Or  InNamedPolygon('SIGNAL_LAYER_1_VM_P040') Or  InNamedPolygon('TOP_LAYER_VM_P038') Or  InNamedPolygon('BOTTOM_LAYER_VM_P036') Or  InNamedPolygon('SIGNAL_LAYER_2_VM_P018') Or  InNamedPolygon('SIGNAL_LAYER_1_VM_P016') Or  InNamedPolygon('TOP_LAYER_VM_P002')] p85: gap=0.254 ignorepadtopadclearanceinfootprint=TRUE except(0: Arc-Hole Track-Hole SMDPad-Hole THPad-Hole Via-Hole Fill-Hole Poly-Hole Region-Hole Text-Hole)
Clearance Clearance_7 [InNamedPolygon('TOP_LAYER_NONET_P089') Or  InNamedPolygon('TOP_LAYER_NONET_P090')] p86: gap=0.254 ignorepadtopadclearanceinfootprint=TRUE except(0: Arc-Hole Track-Hole SMDPad-Hole THPad-Hole Via-Hole Fill-Hole Poly-Hole Region-Hole Text-Hole)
